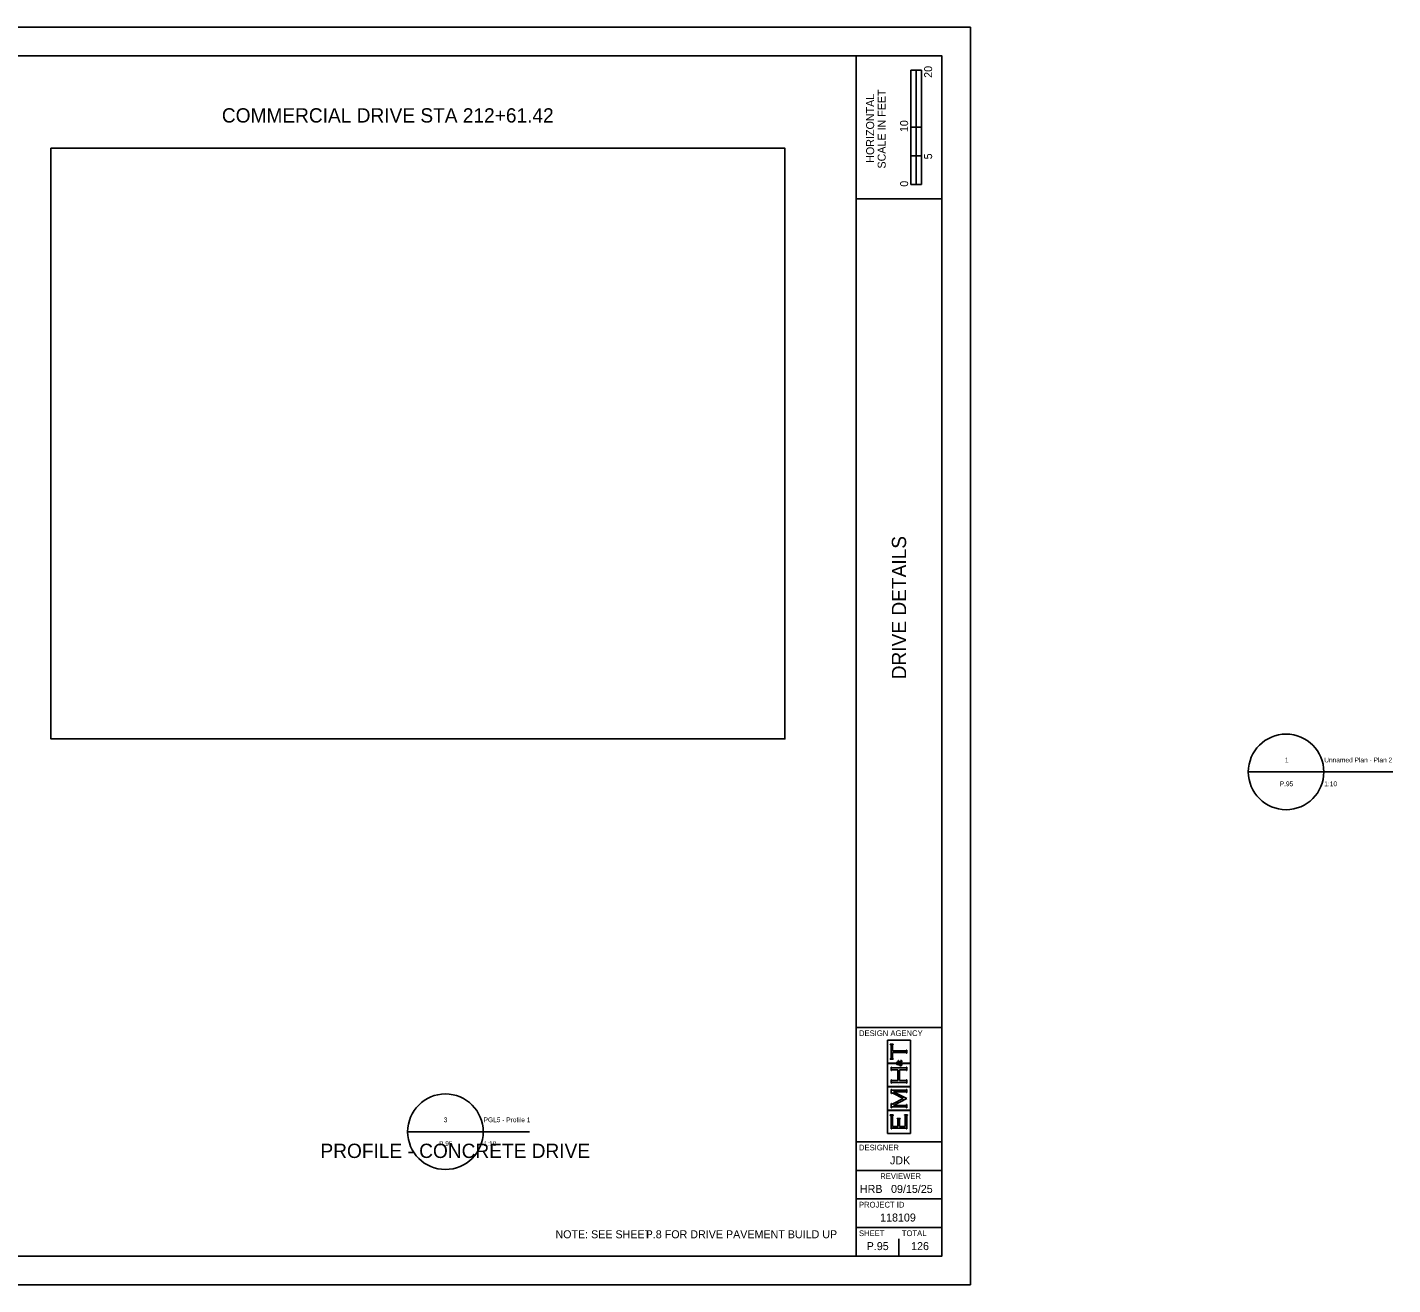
# Model space of a CAD drawing. Extents: x 0 to 41.4, y -6.6 to 22.
# Drawn here: x 17.5 to 41.39, y 0 to 22 of the extents above; entities that cross this region are included whole.
import ezdxf

# ---------------------------------------------------------------- set-up
doc = ezdxf.new("R2010")
doc.units = 0
for name, color, linetype in [('SC_Scratch1', 7, 'Continuous'), ('SH_Border', 7, 'Continuous'), ('SH_Cut_Line', 7, 'Continuous'), ('SH_Data', 7, 'Continuous'), ('SH_Text', 7, 'Continuous')]:
    doc.layers.add(name, color=color, linetype=linetype)

msp = doc.modelspace()

# ---------------------------------------------------------------- linework, layer by layer
at = {"layer": 'SC_Scratch1'}
for p, q in [((38.863, 8.972), (40.186, 8.972)), ((39.53, 8.972), (41.39, 8.972)), ((24.151, 2.676), (25.474, 2.676)), ((24.819, 2.676), (26.287, 2.676))]:
    msp.add_line(p, q, dxfattribs=at)
for centre in [(39.524, 8.972), (24.813, 2.676)]:
    msp.add_circle(centre, 0.661, dxfattribs=at)
at = {"layer": 'SH_Border'}
for p, q in [((32, 0.5), (32, 21.5)), ((32, 19), (33.5, 19)), ((32, 4.5), (33.5, 4.5)), ((32, 2.5), (33.5, 2.5)), ((32, 2), (33.5, 2)), ((32, 1.5), (33.5, 1.5)), ((32, 1), (33.5, 1))]:
    msp.add_line(p, q, dxfattribs=at)
msp.add_lwpolyline([(1.5, 21.5), (33.5, 21.5), (33.5, 0.5), (1.5, 0.5)], close=True, dxfattribs=at)
at = {"layer": 'SH_Cut_Line'}
msp.add_lwpolyline([(0, 0), (34, 0), (34, 22), (0, 22)], close=True, dxfattribs=at)
at = {"layer": 'SH_Data'}
for p, q in [((32.957, 19.25), (32.957, 21.25)), ((33.144, 21.25), (32.957, 21.25)), ((32.957, 20.25), (32.957, 21.25)), ((32.957, 21.25), (33.05, 21.25)), ((33.05, 21.25), (33.051, 21.25)), ((33.051, 21.25), (33.051, 20.25)), ((33.144, 21.25), (33.144, 19.25)), ((33.051, 20.25), (32.957, 20.25)), ((33.143, 20.25), (33.05, 20.25)), ((33.05, 20.25), (33.05, 19.75)), ((33.143, 19.75), (33.143, 20.25)), ((33.05, 19.75), (32.957, 19.75)), ((32.957, 19.75), (32.957, 19.25)), ((33.05, 19.75), (33.143, 19.75)), ((33.05, 19.25), (33.05, 19.75)), ((33.144, 19.25), (32.957, 19.25)), ((32.957, 19.25), (33.05, 19.25)), ((32.952, 4.279), (32.547, 4.279)), ((32.547, 4.279), (32.547, 3.875)), ((32.598, 4.204), (32.598, 4.211)), ((32.598, 4.211), (32.65, 4.211)), ((32.603, 4.203), (32.598, 4.204)), ((32.606, 4.201), (32.603, 4.203)), ((32.608, 4.199), (32.606, 4.201)), ((32.61, 4.196), (32.608, 4.199)), ((32.611, 4.192), (32.61, 4.196)), ((32.611, 4.187), (32.611, 4.192)), ((32.611, 3.968), (32.611, 4.187)), ((32.638, 4.196), (32.637, 4.192)), ((32.637, 4.192), (32.637, 4.187)), ((32.637, 4.187), (32.637, 4.093)), ((32.637, 4.093), (32.864, 4.093)), ((32.64, 4.199), (32.638, 4.196)), ((32.642, 4.201), (32.64, 4.199)), ((32.645, 4.203), (32.642, 4.201)), ((32.65, 4.204), (32.645, 4.203)), ((32.65, 4.211), (32.65, 4.204)), ((32.864, 4.093), (32.869, 4.093)), ((32.869, 4.093), (32.873, 4.094)), ((32.873, 4.094), (32.876, 4.096)), ((32.876, 4.096), (32.878, 4.097)), ((32.878, 4.097), (32.88, 4.101)), ((32.88, 4.101), (32.881, 4.106)), ((32.881, 4.106), (32.888, 4.106)), ((32.888, 4.106), (32.888, 4.048)), ((32.952, 3.875), (32.952, 4.279)), ((32.547, 3.875), (32.696, 3.875)), ((32.696, 3.869), (32.547, 3.869)), ((32.547, 3.869), (32.547, 3.465)), ((32.598, 3.95), (32.603, 3.951)), ((32.598, 3.944), (32.598, 3.95)), ((32.65, 3.944), (32.598, 3.944)), ((32.603, 3.951), (32.606, 3.953)), ((32.606, 3.953), (32.608, 3.955)), ((32.608, 3.955), (32.61, 3.958)), ((32.61, 3.958), (32.611, 3.962)), ((32.611, 3.962), (32.611, 3.968)), ((32.864, 4.061), (32.637, 4.061)), ((32.637, 4.061), (32.637, 3.968)), ((32.637, 3.968), (32.637, 3.962)), ((32.637, 3.962), (32.638, 3.958)), ((32.638, 3.958), (32.64, 3.955)), ((32.64, 3.955), (32.642, 3.953)), ((32.642, 3.953), (32.645, 3.951)), ((32.645, 3.951), (32.65, 3.95)), ((32.65, 3.95), (32.65, 3.944)), ((32.696, 3.875), (32.696, 3.869)), ((32.703, 3.879), (32.705, 3.883)), ((32.703, 3.873), (32.703, 3.879)), ((32.703, 3.868), (32.703, 3.873)), ((32.705, 3.863), (32.703, 3.868)), ((32.705, 3.883), (32.708, 3.887)), ((32.708, 3.858), (32.705, 3.863)), ((32.708, 3.887), (32.711, 3.89)), ((32.709, 3.879), (32.708, 3.876)), ((32.708, 3.876), (32.708, 3.873)), ((32.708, 3.873), (32.708, 3.869)), ((32.708, 3.869), (32.71, 3.866)), ((32.712, 3.853), (32.708, 3.858)), ((32.712, 3.881), (32.709, 3.879)), ((32.71, 3.866), (32.712, 3.864)), ((32.711, 3.89), (32.715, 3.892)), ((32.714, 3.883), (32.712, 3.881)), ((32.712, 3.864), (32.715, 3.862)), ((32.718, 3.85), (32.712, 3.853)), ((32.716, 3.884), (32.714, 3.883)), ((32.715, 3.892), (32.72, 3.892)), ((32.715, 3.862), (32.718, 3.861)), ((32.72, 3.884), (32.716, 3.884)), ((32.718, 3.861), (32.721, 3.861)), ((32.726, 3.85), (32.718, 3.85)), ((32.72, 3.892), (32.725, 3.892)), ((32.724, 3.884), (32.72, 3.884)), ((32.721, 3.861), (32.723, 3.861)), ((32.723, 3.861), (32.725, 3.862)), ((32.728, 3.882), (32.724, 3.884)), ((32.725, 3.892), (32.729, 3.89)), ((32.725, 3.862), (32.728, 3.862)), ((32.729, 3.85), (32.726, 3.85)), ((32.731, 3.88), (32.728, 3.882)), ((32.728, 3.862), (32.731, 3.863)), ((32.729, 3.89), (32.732, 3.887)), ((32.731, 3.85), (32.729, 3.85)), ((32.734, 3.877), (32.731, 3.88)), ((32.731, 3.863), (32.735, 3.865)), ((32.734, 3.851), (32.731, 3.85)), ((32.732, 3.887), (32.736, 3.883)), ((32.737, 3.872), (32.734, 3.877)), ((32.737, 3.852), (32.734, 3.851)), ((32.735, 3.865), (32.74, 3.867)), ((32.736, 3.883), (32.74, 3.878)), ((32.74, 3.867), (32.737, 3.872)), ((32.741, 3.853), (32.737, 3.852)), ((32.738, 3.893), (32.738, 3.922)), ((32.738, 3.922), (32.741, 3.922)), ((32.741, 3.893), (32.738, 3.893)), ((32.74, 3.878), (32.744, 3.869)), ((32.741, 3.922), (32.741, 3.918)), ((32.741, 3.918), (32.742, 3.915)), ((32.742, 3.896), (32.741, 3.895)), ((32.741, 3.895), (32.741, 3.893)), ((32.746, 3.855), (32.741, 3.853)), ((32.742, 3.915), (32.743, 3.913)), ((32.743, 3.897), (32.742, 3.896)), ((32.743, 3.913), (32.745, 3.911)), ((32.745, 3.899), (32.743, 3.897)), ((32.744, 3.869), (32.754, 3.875)), ((32.745, 3.911), (32.749, 3.908)), ((32.746, 3.899), (32.745, 3.899)), ((32.748, 3.899), (32.746, 3.899)), ((32.752, 3.844), (32.746, 3.855)), ((32.755, 3.899), (32.748, 3.899)), ((32.749, 3.908), (32.756, 3.904)), ((32.756, 3.86), (32.751, 3.857)), ((32.751, 3.857), (32.754, 3.852)), ((32.757, 3.837), (32.752, 3.844)), ((32.754, 3.875), (32.764, 3.881)), ((32.754, 3.852), (32.757, 3.848)), ((32.763, 3.895), (32.755, 3.899)), ((32.756, 3.904), (32.763, 3.9)), ((32.761, 3.863), (32.756, 3.86)), ((32.757, 3.848), (32.761, 3.845)), ((32.763, 3.833), (32.757, 3.837)), ((32.764, 3.865), (32.761, 3.863)), ((32.761, 3.845), (32.765, 3.843)), ((32.763, 3.9), (32.77, 3.896)), ((32.772, 3.887), (32.763, 3.895)), ((32.768, 3.829), (32.763, 3.833)), ((32.764, 3.881), (32.772, 3.887)), ((32.768, 3.867), (32.764, 3.865)), ((32.765, 3.843), (32.769, 3.841)), ((32.774, 3.872), (32.768, 3.867)), ((32.774, 3.827), (32.768, 3.829)), ((32.769, 3.841), (32.773, 3.841)), ((32.77, 3.896), (32.776, 3.891)), ((32.773, 3.841), (32.778, 3.841)), ((32.782, 3.878), (32.774, 3.872)), ((32.779, 3.827), (32.774, 3.827)), ((32.776, 3.891), (32.781, 3.895)), ((32.778, 3.841), (32.782, 3.843)), ((32.779, 3.923), (32.781, 3.926)), ((32.782, 3.922), (32.779, 3.923)), ((32.785, 3.827), (32.779, 3.827)), ((32.781, 3.926), (32.787, 3.924)), ((32.781, 3.895), (32.784, 3.898)), ((32.785, 3.921), (32.782, 3.922)), ((32.786, 3.873), (32.782, 3.878)), ((32.782, 3.843), (32.786, 3.846)), ((32.784, 3.898), (32.786, 3.901)), ((32.786, 3.919), (32.785, 3.921)), ((32.79, 3.829), (32.785, 3.827)), ((32.788, 3.917), (32.786, 3.919)), ((32.786, 3.901), (32.788, 3.904)), ((32.791, 3.886), (32.786, 3.881)), ((32.786, 3.881), (32.791, 3.876)), ((32.788, 3.869), (32.786, 3.873)), ((32.786, 3.846), (32.789, 3.849)), ((32.787, 3.924), (32.792, 3.921)), ((32.789, 3.914), (32.788, 3.917)), ((32.788, 3.904), (32.789, 3.908)), ((32.79, 3.867), (32.788, 3.869)), ((32.789, 3.911), (32.789, 3.914)), ((32.789, 3.908), (32.789, 3.911)), ((32.789, 3.849), (32.791, 3.853)), ((32.791, 3.864), (32.79, 3.867)), ((32.793, 3.834), (32.79, 3.829)), ((32.794, 3.89), (32.791, 3.886)), ((32.791, 3.876), (32.795, 3.87)), ((32.791, 3.861), (32.791, 3.864)), ((32.791, 3.859), (32.791, 3.861)), ((32.791, 3.853), (32.791, 3.859)), ((32.792, 3.921), (32.795, 3.918)), ((32.797, 3.838), (32.793, 3.834)), ((32.796, 3.894), (32.794, 3.89)), ((32.795, 3.918), (32.798, 3.914)), ((32.795, 3.87), (32.797, 3.866)), ((32.798, 3.897), (32.796, 3.894)), ((32.797, 3.866), (32.798, 3.861)), ((32.799, 3.844), (32.797, 3.838)), ((32.798, 3.914), (32.799, 3.91)), ((32.799, 3.901), (32.798, 3.897)), ((32.798, 3.861), (32.799, 3.857)), ((32.799, 3.91), (32.799, 3.905)), ((32.799, 3.905), (32.799, 3.901)), ((32.803, 3.869), (32.799, 3.875)), ((32.799, 3.875), (32.952, 3.875)), ((32.799, 3.857), (32.799, 3.852)), ((32.799, 3.852), (32.799, 3.844)), ((32.952, 3.869), (32.803, 3.869)), ((32.87, 4.061), (32.864, 4.061)), ((32.874, 4.06), (32.87, 4.061)), ((32.876, 4.059), (32.874, 4.06)), ((32.878, 4.057), (32.876, 4.059)), ((32.88, 4.053), (32.878, 4.057)), ((32.881, 4.048), (32.88, 4.053)), ((32.888, 4.048), (32.881, 4.048)), ((32.952, 3.465), (32.952, 3.869)), ((32.611, 3.749), (32.611, 3.807)), ((32.611, 3.807), (32.617, 3.807)), ((32.617, 3.749), (32.611, 3.749)), ((32.611, 3.527), (32.611, 3.585)), ((32.611, 3.585), (32.617, 3.585)), ((32.617, 3.807), (32.619, 3.802)), ((32.618, 3.754), (32.617, 3.749)), ((32.617, 3.585), (32.619, 3.58)), ((32.62, 3.758), (32.618, 3.754)), ((32.619, 3.802), (32.62, 3.798)), ((32.62, 3.798), (32.623, 3.797)), ((32.623, 3.76), (32.62, 3.758)), ((32.623, 3.797), (32.625, 3.795)), ((32.625, 3.761), (32.623, 3.76)), ((32.625, 3.795), (32.629, 3.794)), ((32.629, 3.762), (32.625, 3.761)), ((32.629, 3.794), (32.635, 3.794)), ((32.635, 3.762), (32.629, 3.762)), ((32.635, 3.794), (32.864, 3.794)), ((32.732, 3.762), (32.635, 3.762)), ((32.732, 3.572), (32.732, 3.762)), ((32.864, 3.762), (32.759, 3.762)), ((32.759, 3.762), (32.759, 3.572)), ((32.864, 3.794), (32.869, 3.794)), ((32.87, 3.762), (32.864, 3.762)), ((32.869, 3.794), (32.873, 3.795)), ((32.874, 3.761), (32.87, 3.762)), ((32.873, 3.795), (32.876, 3.797)), ((32.876, 3.76), (32.874, 3.761)), ((32.876, 3.797), (32.878, 3.798)), ((32.878, 3.758), (32.876, 3.76)), ((32.878, 3.798), (32.88, 3.802)), ((32.88, 3.754), (32.878, 3.758)), ((32.88, 3.802), (32.881, 3.807)), ((32.881, 3.749), (32.88, 3.754)), ((32.88, 3.58), (32.881, 3.585)), ((32.881, 3.807), (32.888, 3.807)), ((32.888, 3.749), (32.881, 3.749)), ((32.881, 3.585), (32.888, 3.585)), ((32.888, 3.807), (32.888, 3.749)), ((32.888, 3.585), (32.888, 3.527)), ((32.547, 3.465), (32.952, 3.465)), ((32.952, 3.459), (32.547, 3.459)), ((32.547, 3.459), (32.547, 3.055)), ((32.617, 3.527), (32.611, 3.527)), ((32.611, 3.345), (32.611, 3.418)), ((32.611, 3.418), (32.617, 3.418)), ((32.617, 3.345), (32.611, 3.345)), ((32.618, 3.532), (32.617, 3.527)), ((32.617, 3.418), (32.619, 3.412)), ((32.62, 3.352), (32.617, 3.345)), ((32.62, 3.536), (32.618, 3.532)), ((32.619, 3.58), (32.62, 3.576)), ((32.619, 3.412), (32.62, 3.409)), ((32.62, 3.576), (32.623, 3.574)), ((32.623, 3.537), (32.62, 3.536)), ((32.62, 3.409), (32.623, 3.407)), ((32.622, 3.355), (32.62, 3.352)), ((32.626, 3.355), (32.622, 3.355)), ((32.623, 3.574), (32.625, 3.573)), ((32.625, 3.539), (32.623, 3.537)), ((32.623, 3.407), (32.625, 3.405)), ((32.625, 3.573), (32.629, 3.572)), ((32.629, 3.54), (32.625, 3.539)), ((32.625, 3.405), (32.629, 3.405)), ((32.629, 3.355), (32.626, 3.355)), ((32.629, 3.572), (32.635, 3.572)), ((32.635, 3.54), (32.629, 3.54)), ((32.629, 3.405), (32.635, 3.405)), ((32.633, 3.353), (32.629, 3.355)), ((32.64, 3.35), (32.633, 3.353)), ((32.635, 3.572), (32.732, 3.572)), ((32.864, 3.54), (32.635, 3.54)), ((32.635, 3.405), (32.864, 3.405)), ((32.825, 3.257), (32.64, 3.35)), ((32.864, 3.373), (32.654, 3.373)), ((32.654, 3.373), (32.888, 3.255)), ((32.75, 3.5), (32.75, 3.5)), ((32.759, 3.572), (32.864, 3.572)), ((32.864, 3.572), (32.87, 3.572)), ((32.87, 3.54), (32.864, 3.54)), ((32.864, 3.405), (32.869, 3.405)), ((32.87, 3.373), (32.864, 3.373)), ((32.869, 3.405), (32.873, 3.405)), ((32.87, 3.572), (32.874, 3.573)), ((32.874, 3.539), (32.87, 3.54)), ((32.874, 3.372), (32.87, 3.373)), ((32.873, 3.405), (32.876, 3.407)), ((32.874, 3.573), (32.876, 3.574)), ((32.876, 3.538), (32.874, 3.539)), ((32.876, 3.37), (32.874, 3.372)), ((32.876, 3.574), (32.878, 3.576)), ((32.878, 3.536), (32.876, 3.538)), ((32.876, 3.407), (32.878, 3.409)), ((32.878, 3.369), (32.876, 3.37)), ((32.878, 3.576), (32.88, 3.58)), ((32.88, 3.532), (32.878, 3.536)), ((32.878, 3.409), (32.88, 3.412)), ((32.88, 3.365), (32.878, 3.369)), ((32.881, 3.527), (32.88, 3.532)), ((32.88, 3.412), (32.881, 3.418)), ((32.881, 3.36), (32.88, 3.365)), ((32.888, 3.527), (32.881, 3.527)), ((32.881, 3.418), (32.888, 3.418)), ((32.888, 3.36), (32.881, 3.36)), ((32.888, 3.418), (32.888, 3.36)), ((32.952, 3.055), (32.952, 3.459)), ((32.611, 3.096), (32.611, 3.168)), ((32.611, 3.168), (32.617, 3.168)), ((32.617, 3.168), (32.62, 3.162)), ((32.62, 3.162), (32.622, 3.158)), ((32.623, 3.107), (32.62, 3.105)), ((32.622, 3.158), (32.626, 3.158)), ((32.625, 3.109), (32.623, 3.107)), ((32.629, 3.109), (32.625, 3.109)), ((32.626, 3.158), (32.627, 3.158)), ((32.627, 3.158), (32.633, 3.161)), ((32.635, 3.109), (32.629, 3.109)), ((32.633, 3.161), (32.641, 3.165)), ((32.864, 3.109), (32.635, 3.109)), ((32.641, 3.165), (32.825, 3.257)), ((32.888, 3.255), (32.654, 3.138)), ((32.654, 3.138), (32.864, 3.138)), ((32.864, 3.138), (32.869, 3.138)), ((32.87, 3.109), (32.864, 3.109)), ((32.869, 3.138), (32.873, 3.139)), ((32.874, 3.109), (32.87, 3.109)), ((32.873, 3.139), (32.876, 3.141)), ((32.876, 3.107), (32.874, 3.109)), ((32.876, 3.141), (32.878, 3.143)), ((32.878, 3.105), (32.876, 3.107)), ((32.878, 3.143), (32.88, 3.146)), ((32.88, 3.146), (32.881, 3.151)), ((32.881, 3.151), (32.888, 3.151)), ((32.888, 3.151), (32.888, 3.096)), ((32.547, 3.055), (32.952, 3.055)), ((32.952, 3.049), (32.547, 3.049)), ((32.547, 3.049), (32.547, 2.645)), ((32.598, 2.962), (32.598, 2.969)), ((32.598, 2.969), (32.65, 2.969)), ((32.603, 2.961), (32.598, 2.962)), ((32.606, 2.959), (32.603, 2.961)), ((32.608, 2.957), (32.606, 2.959)), ((32.61, 2.955), (32.608, 2.957)), ((32.611, 2.951), (32.61, 2.955)), ((32.617, 3.096), (32.611, 3.096)), ((32.611, 2.945), (32.611, 2.951)), ((32.611, 2.725), (32.611, 2.945)), ((32.618, 3.102), (32.617, 3.096)), ((32.62, 3.105), (32.618, 3.102)), ((32.64, 2.957), (32.638, 2.955)), ((32.638, 2.955), (32.638, 2.951)), ((32.638, 2.951), (32.638, 2.945)), ((32.638, 2.945), (32.638, 2.77)), ((32.642, 2.959), (32.64, 2.957)), ((32.645, 2.961), (32.642, 2.959)), ((32.65, 2.962), (32.645, 2.961)), ((32.65, 2.969), (32.65, 2.962)), ((32.719, 2.902), (32.719, 2.908)), ((32.719, 2.908), (32.772, 2.908)), ((32.724, 2.901), (32.719, 2.902)), ((32.728, 2.899), (32.724, 2.901)), ((32.729, 2.896), (32.728, 2.899)), ((32.731, 2.894), (32.729, 2.896)), ((32.732, 2.89), (32.731, 2.894)), ((32.732, 2.884), (32.732, 2.89)), ((32.732, 2.77), (32.732, 2.884)), ((32.76, 2.894), (32.759, 2.89)), ((32.759, 2.89), (32.759, 2.884)), ((32.759, 2.884), (32.759, 2.77)), ((32.761, 2.896), (32.76, 2.894)), ((32.763, 2.899), (32.761, 2.896)), ((32.767, 2.901), (32.763, 2.899)), ((32.772, 2.902), (32.767, 2.901)), ((32.772, 2.908), (32.772, 2.902)), ((32.848, 2.965), (32.848, 2.972)), ((32.848, 2.972), (32.901, 2.972)), ((32.853, 2.964), (32.848, 2.965)), ((32.857, 2.962), (32.853, 2.964)), ((32.859, 2.96), (32.857, 2.962)), ((32.86, 2.958), (32.859, 2.96)), ((32.861, 2.953), (32.86, 2.958)), ((32.861, 2.948), (32.861, 2.953)), ((32.861, 2.77), (32.861, 2.948)), ((32.88, 3.102), (32.878, 3.105)), ((32.881, 3.096), (32.88, 3.102)), ((32.888, 3.096), (32.881, 3.096)), ((32.889, 2.957), (32.888, 2.953)), ((32.888, 2.953), (32.888, 2.948)), ((32.888, 2.948), (32.888, 2.725)), ((32.891, 2.96), (32.889, 2.957)), ((32.892, 2.962), (32.891, 2.96)), ((32.896, 2.964), (32.892, 2.962)), ((32.901, 2.965), (32.896, 2.964)), ((32.901, 2.972), (32.901, 2.965)), ((32.952, 2.645), (32.952, 3.049)), ((32.547, 2.645), (32.952, 2.645)), ((32.617, 2.725), (32.611, 2.725)), ((32.619, 2.73), (32.617, 2.725)), ((32.62, 2.734), (32.619, 2.73)), ((32.623, 2.735), (32.62, 2.734)), ((32.625, 2.737), (32.623, 2.735)), ((32.629, 2.738), (32.625, 2.737)), ((32.635, 2.738), (32.629, 2.738)), ((32.864, 2.738), (32.635, 2.738)), ((32.638, 2.77), (32.732, 2.77)), ((32.759, 2.77), (32.861, 2.77)), ((32.87, 2.738), (32.864, 2.738)), ((32.874, 2.737), (32.87, 2.738)), ((32.876, 2.735), (32.874, 2.737)), ((32.878, 2.734), (32.876, 2.735)), ((32.88, 2.73), (32.878, 2.734)), ((32.881, 2.725), (32.88, 2.73)), ((32.888, 2.725), (32.881, 2.725)), ((32.75, 0.5), (32.75, 0.8)), ((32.375, 0.675), (32.375, 0.675))]:
    msp.add_line(p, q, dxfattribs=at)
at = {"layer": 'SH_Text'}
msp.add_lwpolyline([(17.91, 19.885), (30.755, 19.885), (30.755, 9.548), (17.91, 9.548)], close=True, dxfattribs=at)

# ---------------------------------------------------------------- texts
at = {"layer": 'SC_Scratch1'}
for s, height, p in [('1', 0.0833, (39.503, 9.139)), ('Unnamed Plan - Plan 2', 0.08333, (40.192, 9.139)), ('P.95', 0.0833, (39.413, 8.722)), ('1:10', 0.0833, (40.192, 8.722)), ('3', 0.0833, (24.783, 2.843)), ('PGL5 - Profile 1', 0.08333, (25.481, 2.843)), ('P.95', 0.0833, (24.701, 2.426)), ('1:10', 0.0833, (25.481, 2.426))]:
    msp.add_text(s, height=height, dxfattribs=at).set_placement(p)
at = {"layer": 'SH_Data'}
for s, height, p in [('20', 0.14, (33.33, 21.116)), ('HORIZONTAL', 0.14, (32.315, 19.63)), ('SCALE IN FEET', 0.14, (32.517, 19.529)), ('10', 0.14, (32.91, 20.166)), ('5', 0.14, (33.33, 19.69)), ('0', 0.14, (32.91, 19.211)), ('DRIVE DETAILS', 0.25, (32.875, 10.592))]:
    msp.add_text(s, height=height, rotation=90, dxfattribs=at).set_placement(p)
for s, height, p in [('DESIGN AGENCY', 0.1, (32.05, 4.35)), ('DESIGNER', 0.1, (32.05, 2.35)), ('JDK', 0.14, (32.592, 2.105)), ('REVIEWER', 0.1, (32.422, 1.85)), ('HRB', 0.14, (32.066, 1.605)), ('09/15/25', 0.14, (32.611, 1.605)), ('PROJECT ID', 0.1, (32.05, 1.35)), ('118109', 0.14, (32.42, 1.105)), ('SHEET', 0.1, (32.05, 0.85)), ('P.95', 0.14, (32.185, 0.605)), ('TOTAL', 0.1, (32.8, 0.85)), ('126', 0.14, (32.962, 0.605))]:
    msp.add_text(s, height=height, dxfattribs=at).set_placement(p)
at = {"layer": 'SH_Text'}
for s, height, p in [('COMMERCIAL DRIVE STA 212+61.42', 0.25, (20.901, 20.334)), ('PROFILE - CONCRETE DRIVE', 0.25, (22.626, 2.217)), ('NOTE: SEE SHEET ', 0.14, (26.738, 0.812)), ('P.8', 0.14, (28.317, 0.812)), (' FOR DRIVE PAVEMENT BUILD UP', 0.14, (28.599, 0.812))]:
    msp.add_text(s, height=height, dxfattribs=at).set_placement(p)

doc.saveas('drawing.dxf')
